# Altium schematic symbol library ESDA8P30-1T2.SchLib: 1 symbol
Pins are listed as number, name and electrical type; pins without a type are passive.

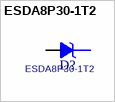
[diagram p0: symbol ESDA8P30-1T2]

## ESDA8P30-1T2
designator D?
footprint ST_SOD882T
pins: 1 K, 2 A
